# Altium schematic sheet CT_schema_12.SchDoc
size 387 x 278 mm
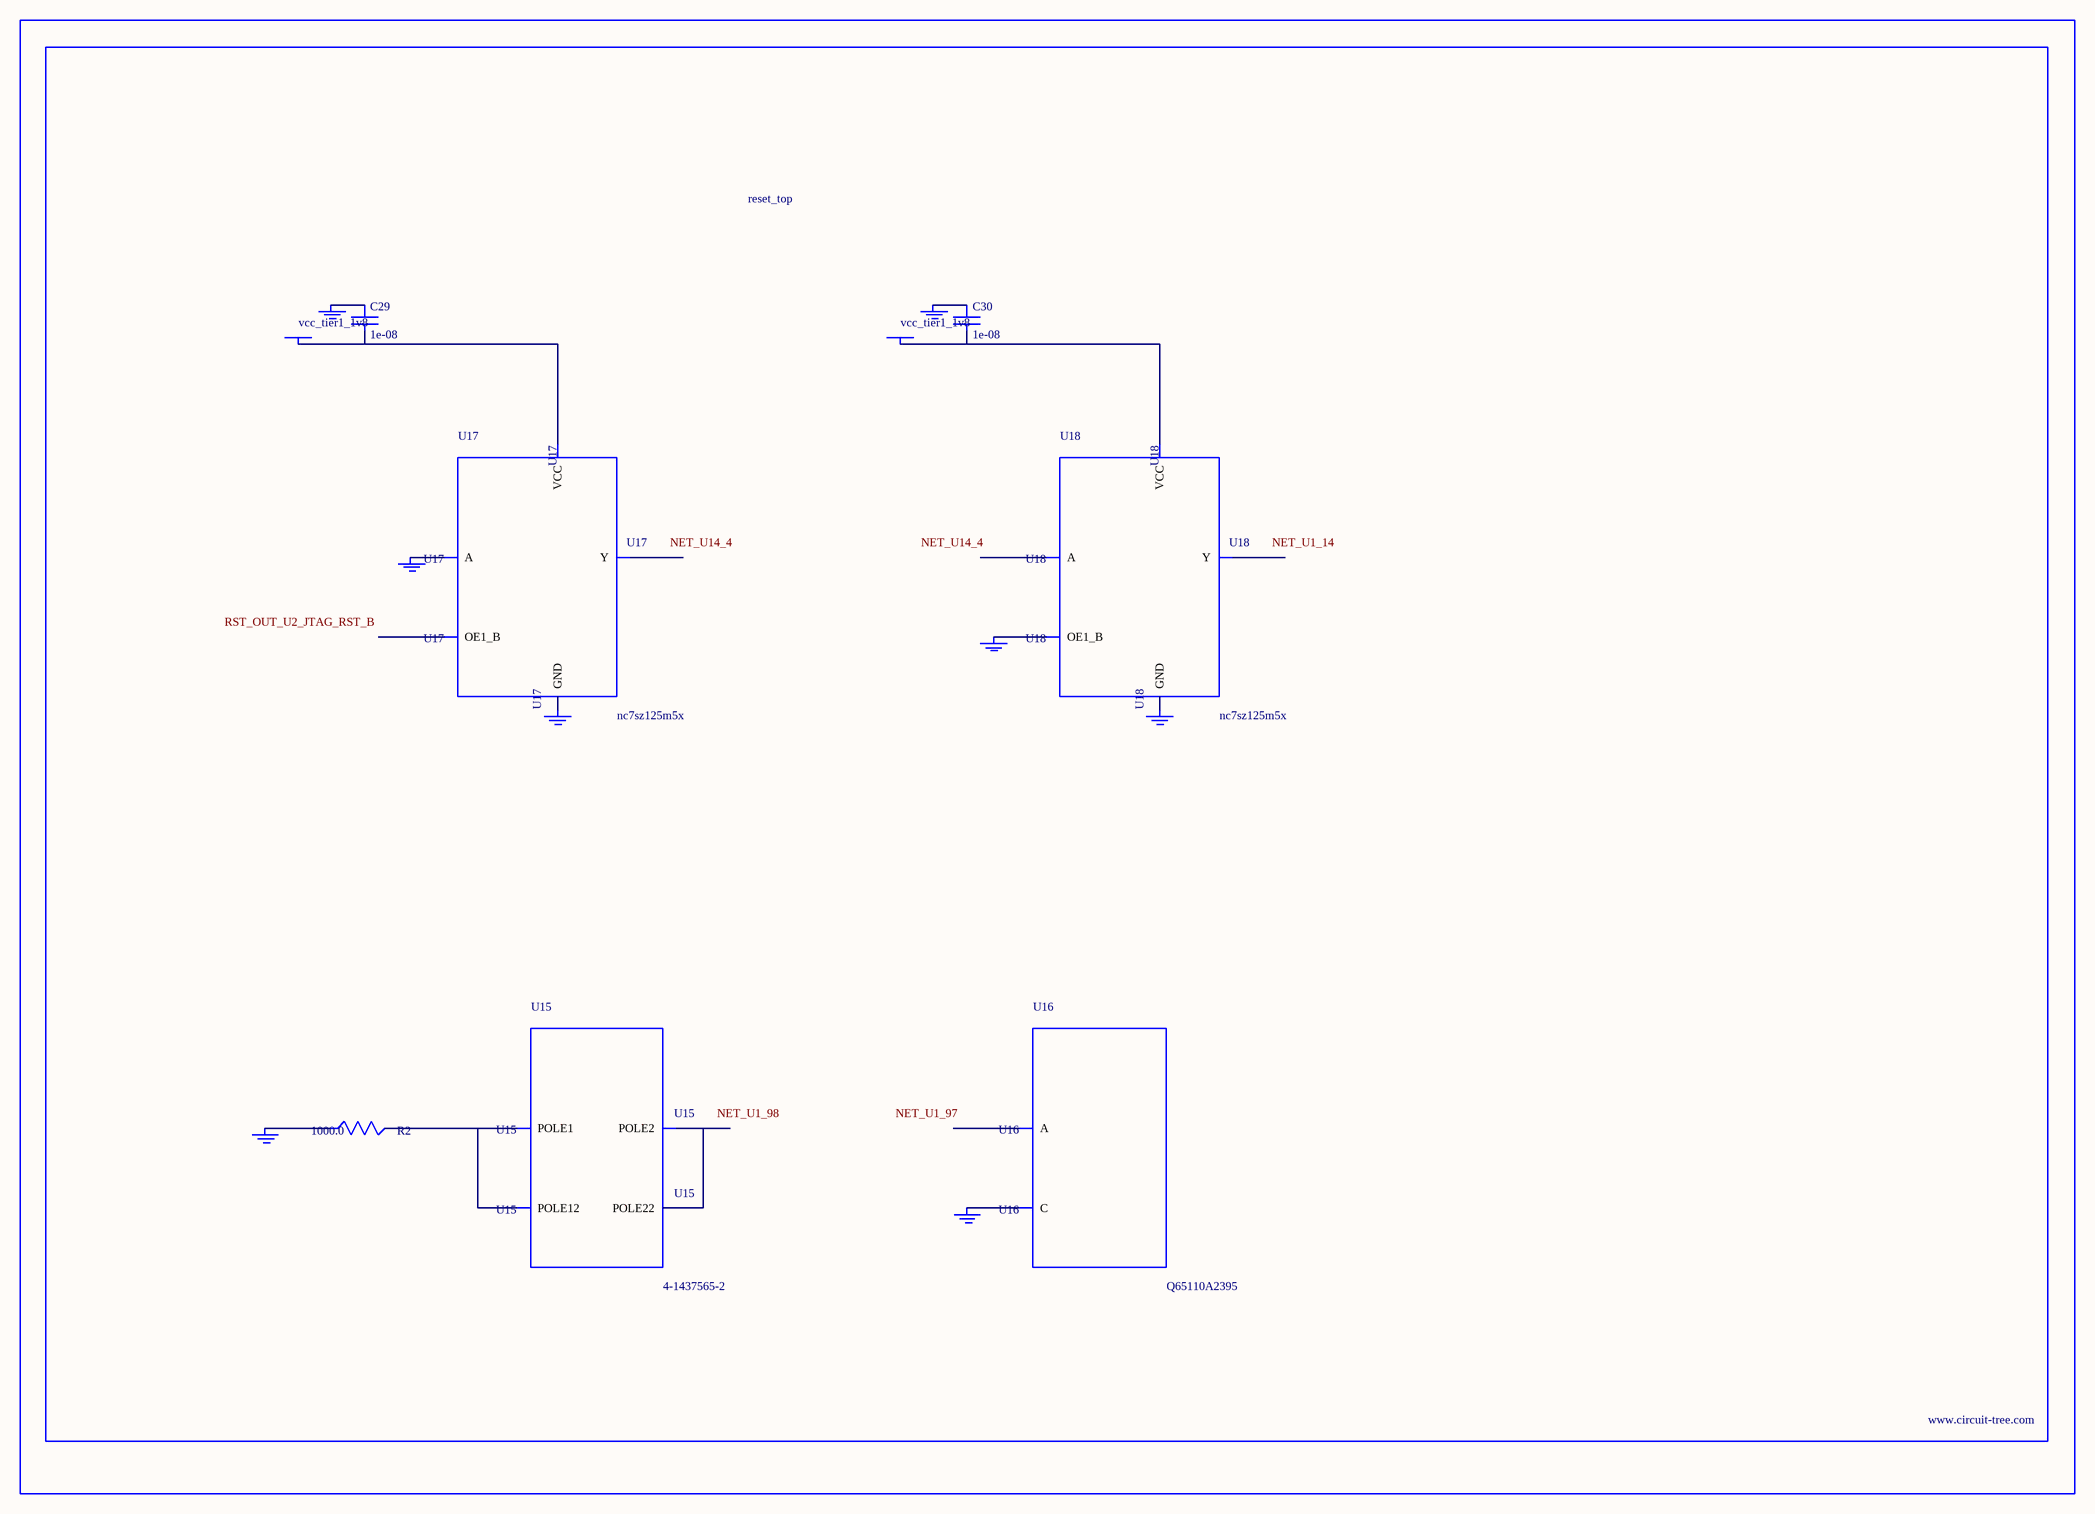
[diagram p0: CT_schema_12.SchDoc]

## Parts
BORDER11  (no value)
C29  1e-08  [C0402]
C30  1e-08  [C0402]
GND_INSTANCE_11_0  (no value)
GND_INSTANCE_11_1  (no value)
GND_INSTANCE_11_2  (no value)
GND_INSTANCE_11_3  (no value)
GND_INSTANCE_11_4  (no value)
GND_INSTANCE_11_5  (no value)
GND_INSTANCE_11_6  (no value)
GND_INSTANCE_11_7  (no value)
POWER_INSTANCE_11_0  vcc_tier1_1v8
POWER_INSTANCE_11_1  vcc_tier1_1v8
R2  1000.0  [R0603]
U15  4-1437565-2  [SW_4-1437565-2]
U16  Q65110A2395  [LGM67K-G1J2-24-Z]
U17  nc7sz125m5x  [NC7SZ125M5X]
U18  nc7sz125m5x  [NC7SZ125M5X]

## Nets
NetC29_1: C29.1 GND_INSTANCE_11_2.0(GND)
NetC29_2: C29.2 POWER_INSTANCE_11_0.0(PWR) U17.5(VCC)
NetC30_1: C30.1 GND_INSTANCE_11_5.0(GND)
NetC30_2: C30.2 POWER_INSTANCE_11_1.0(PWR) U18.5(VCC)
NetGND_INSTANCE_11_0_0: GND_INSTANCE_11_0.0(GND) R2.1
NetGND_INSTANCE_11_1_0: GND_INSTANCE_11_1.0(GND) U16.C
NetGND_INSTANCE_11_3_0: GND_INSTANCE_11_3.0(GND) U17.2(A)
NetGND_INSTANCE_11_4_0: GND_INSTANCE_11_4.0(GND) U17.3(GND)
NetGND_INSTANCE_11_6_0: GND_INSTANCE_11_6.0(GND) U18.1(OE1_B)
NetGND_INSTANCE_11_7_0: GND_INSTANCE_11_7.0(GND) U18.3(GND)
NetR2_2: R2.2 U15.1(POLE1) U15.2(POLE12)
NetU15_3: U15.3(POLE2) U15.4(POLE22)

Not connected (* = marked no-connect by the designer): U16 A; U17 1(OE1_B) 4(Y); U18 2(A) 4(Y)

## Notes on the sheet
- Labels drawn without touching a wire or pin: NET_U1_14, NET_U1_97, NET_U1_98, NET_U14_4, RST_OUT_U2_JTAG_RST_B

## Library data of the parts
BORDER11 = BORDER_PAGE11
C29 C30 = C0402C103K3RAC
GND_INSTANCE_11_0-GND_INSTANCE_11_7 = GND
POWER_INSTANCE_11_0 POWER_INSTANCE_11_1 = PWR
R2 = RC0603JR-071KL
